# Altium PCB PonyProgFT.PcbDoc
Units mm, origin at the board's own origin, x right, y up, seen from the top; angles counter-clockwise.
Board outline 49.5 x 49.5 mm, 4 copper layers (L1_Top, L2_GND, L3_Power, L4_Bottom), stack 1.543 mm thick; 88 components, 68 nets, 308 pads, 119 vias.
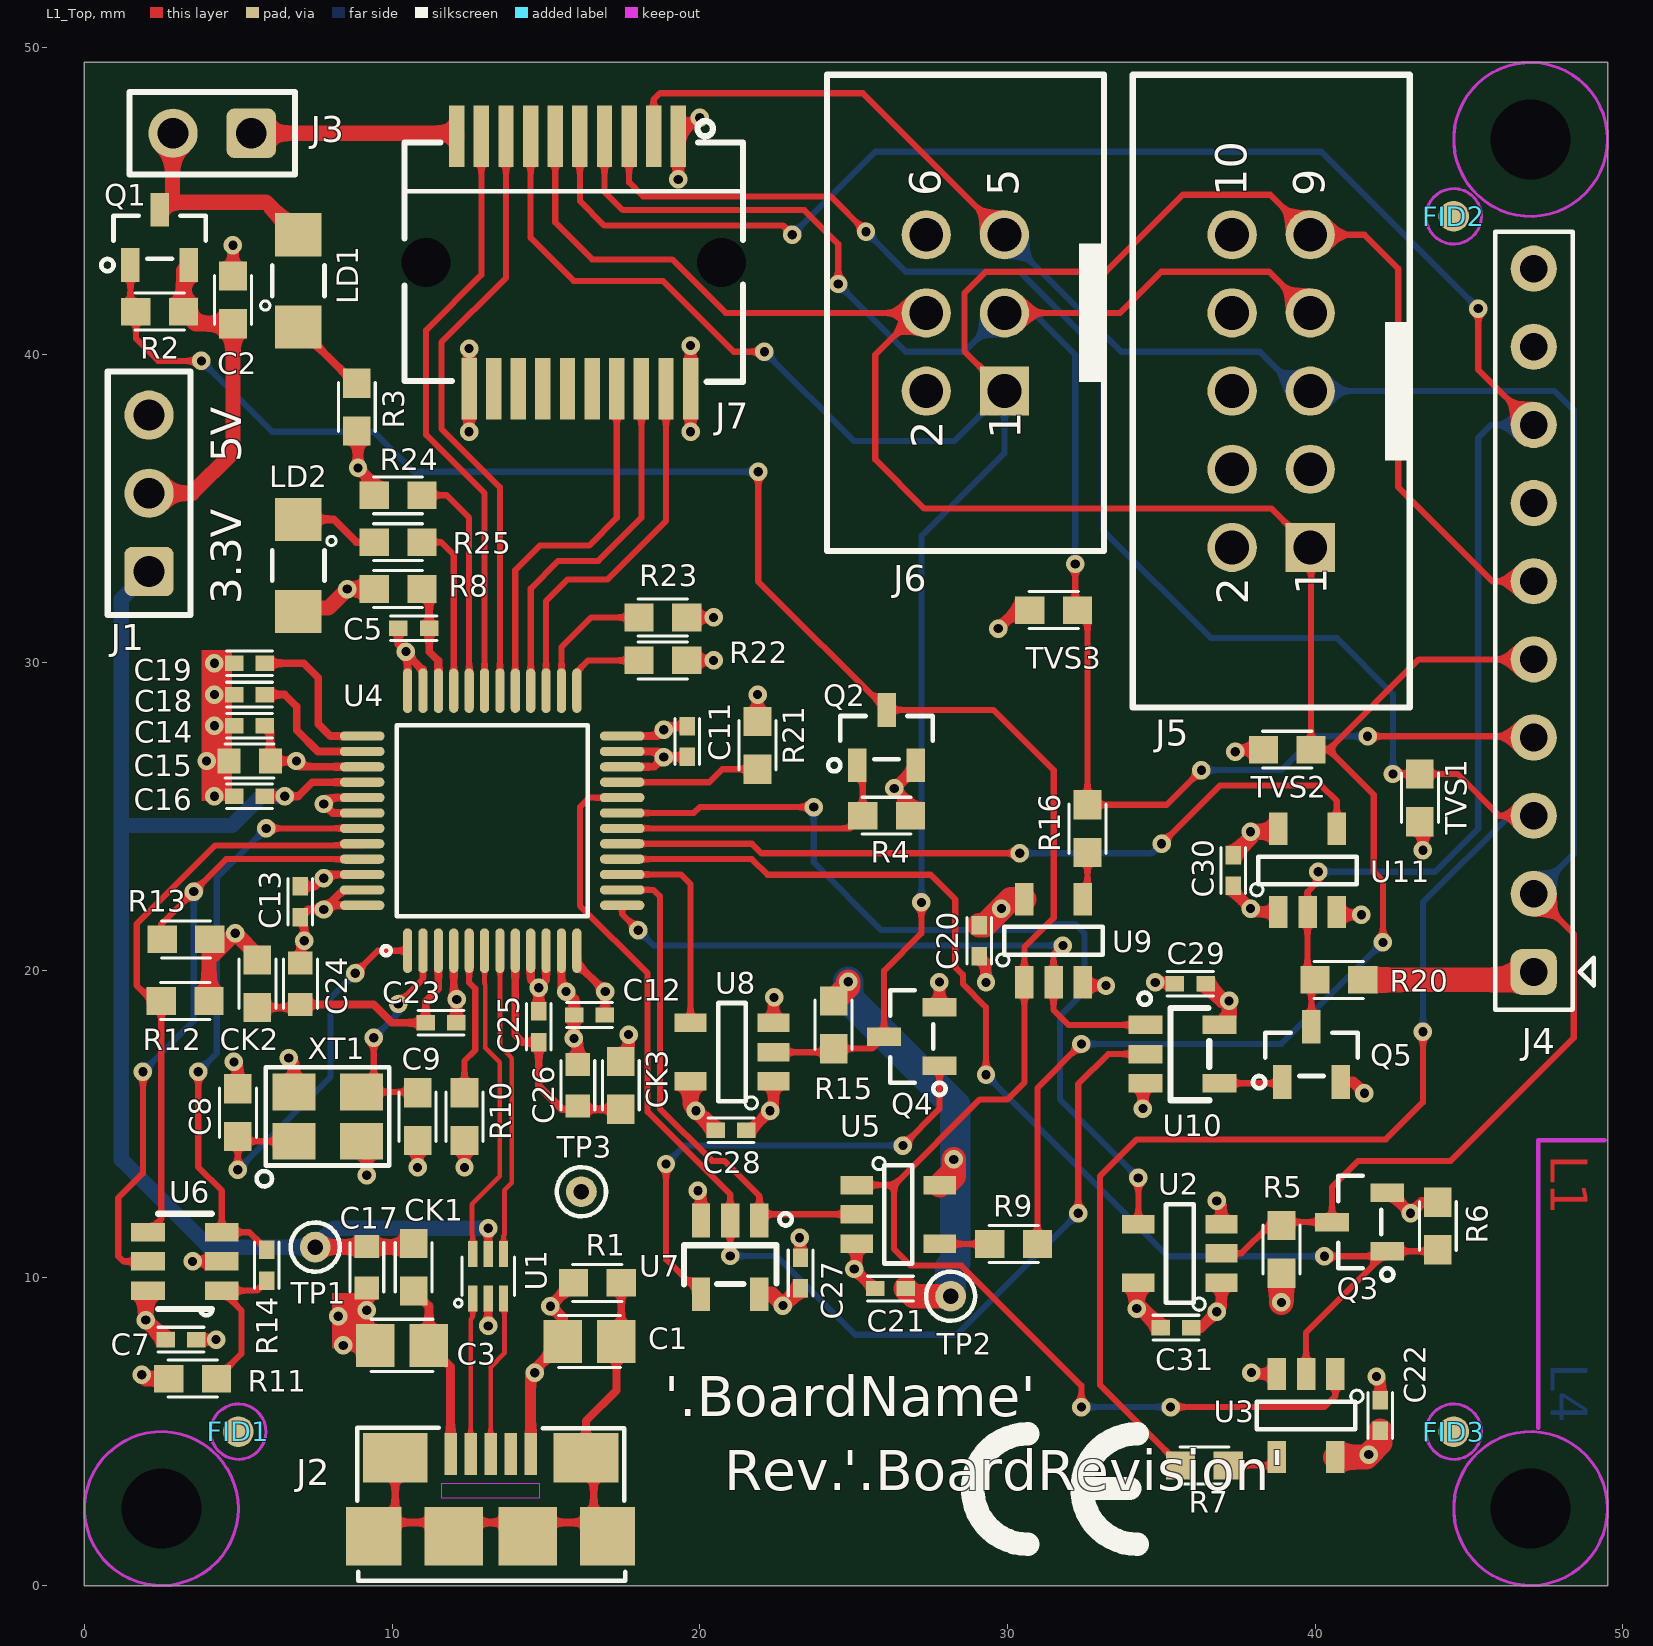
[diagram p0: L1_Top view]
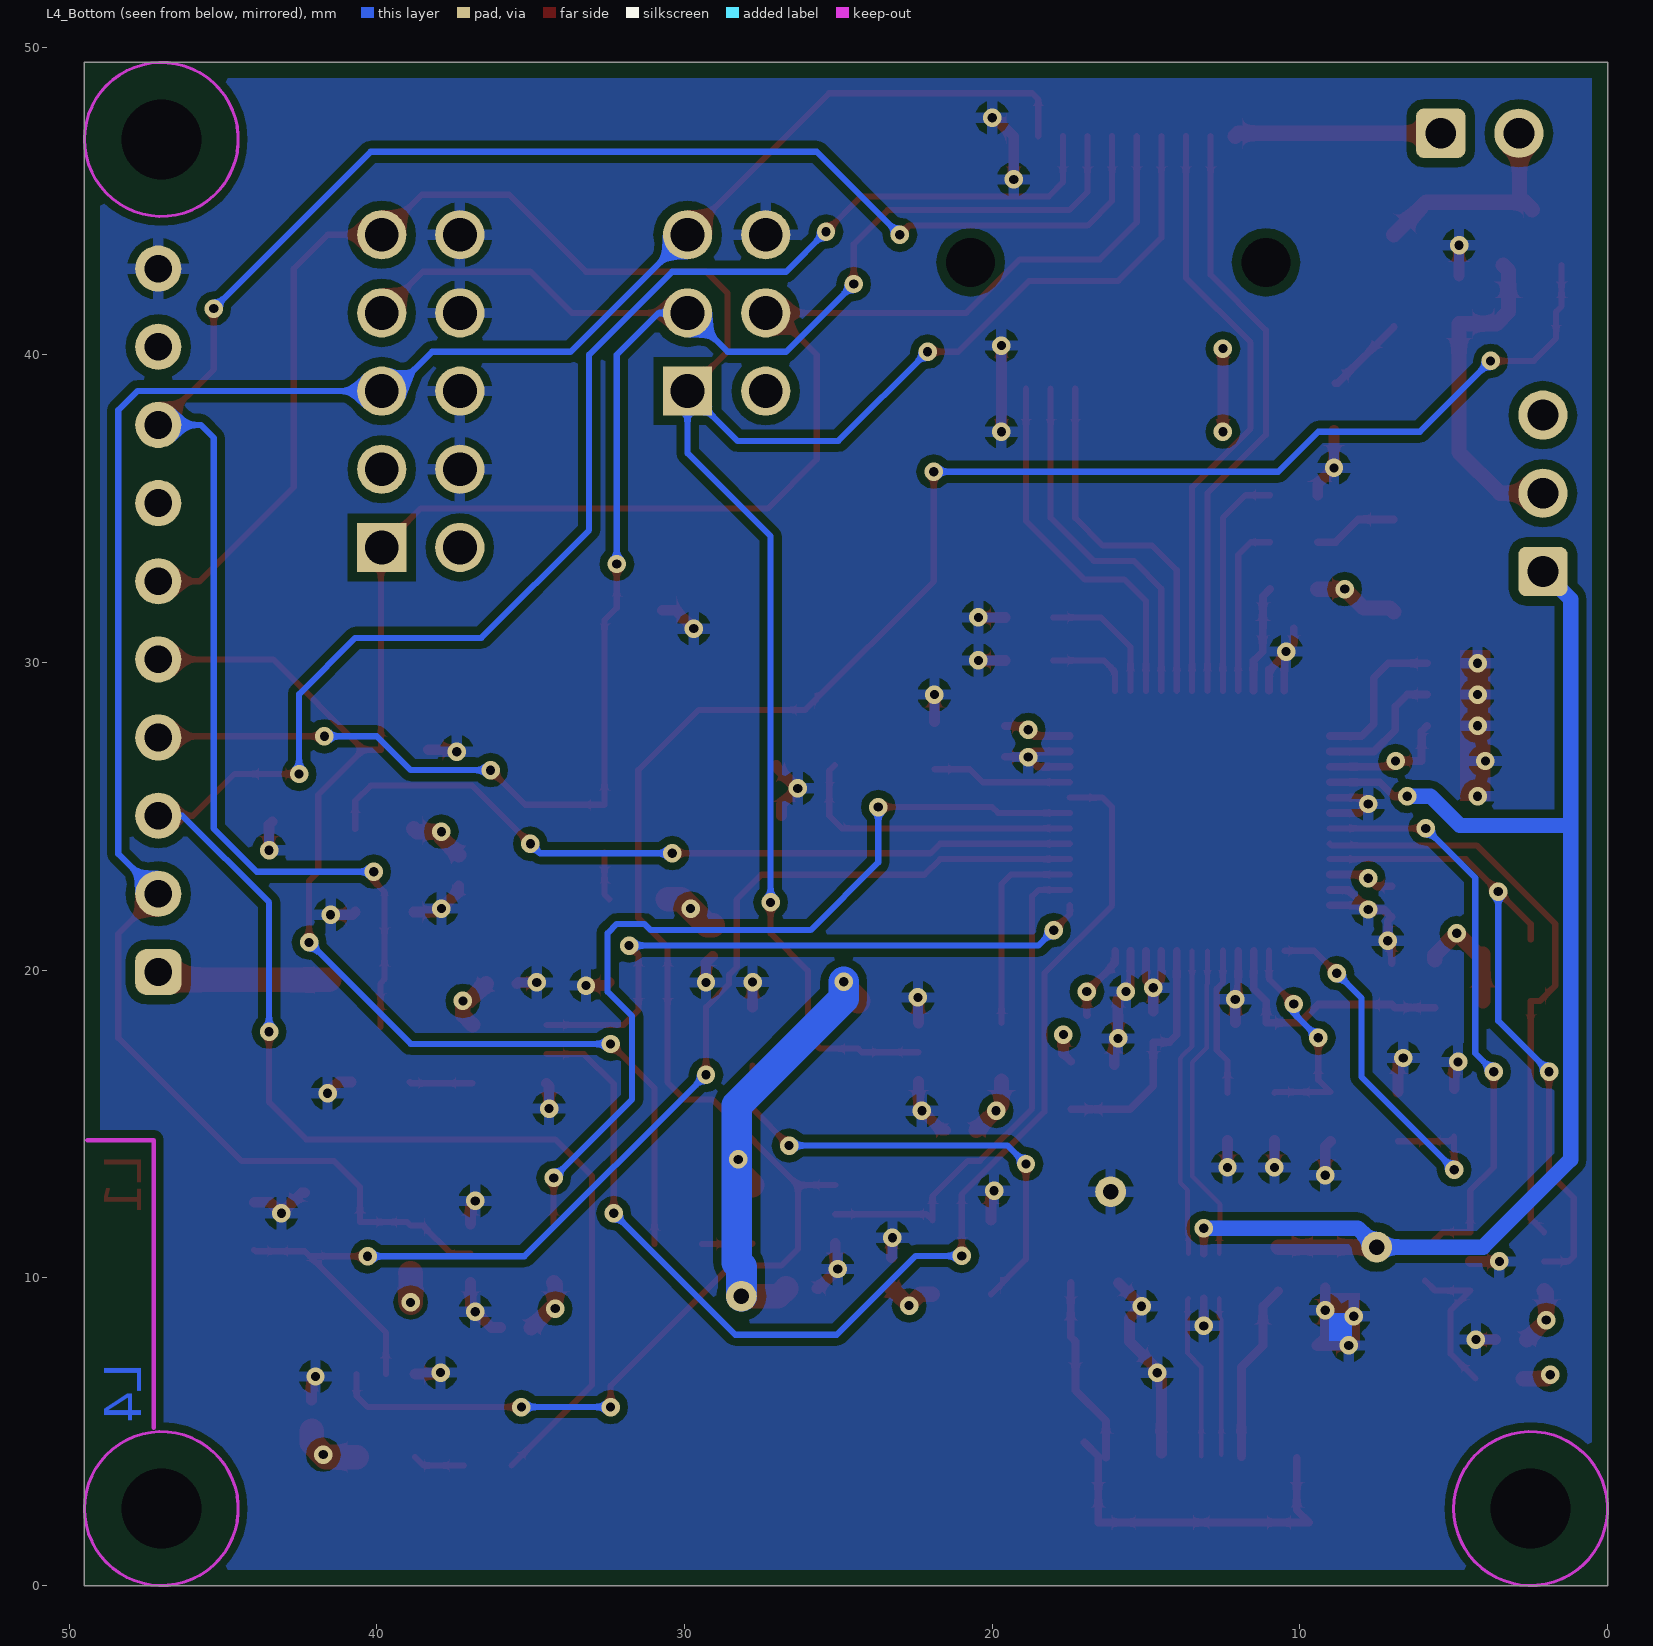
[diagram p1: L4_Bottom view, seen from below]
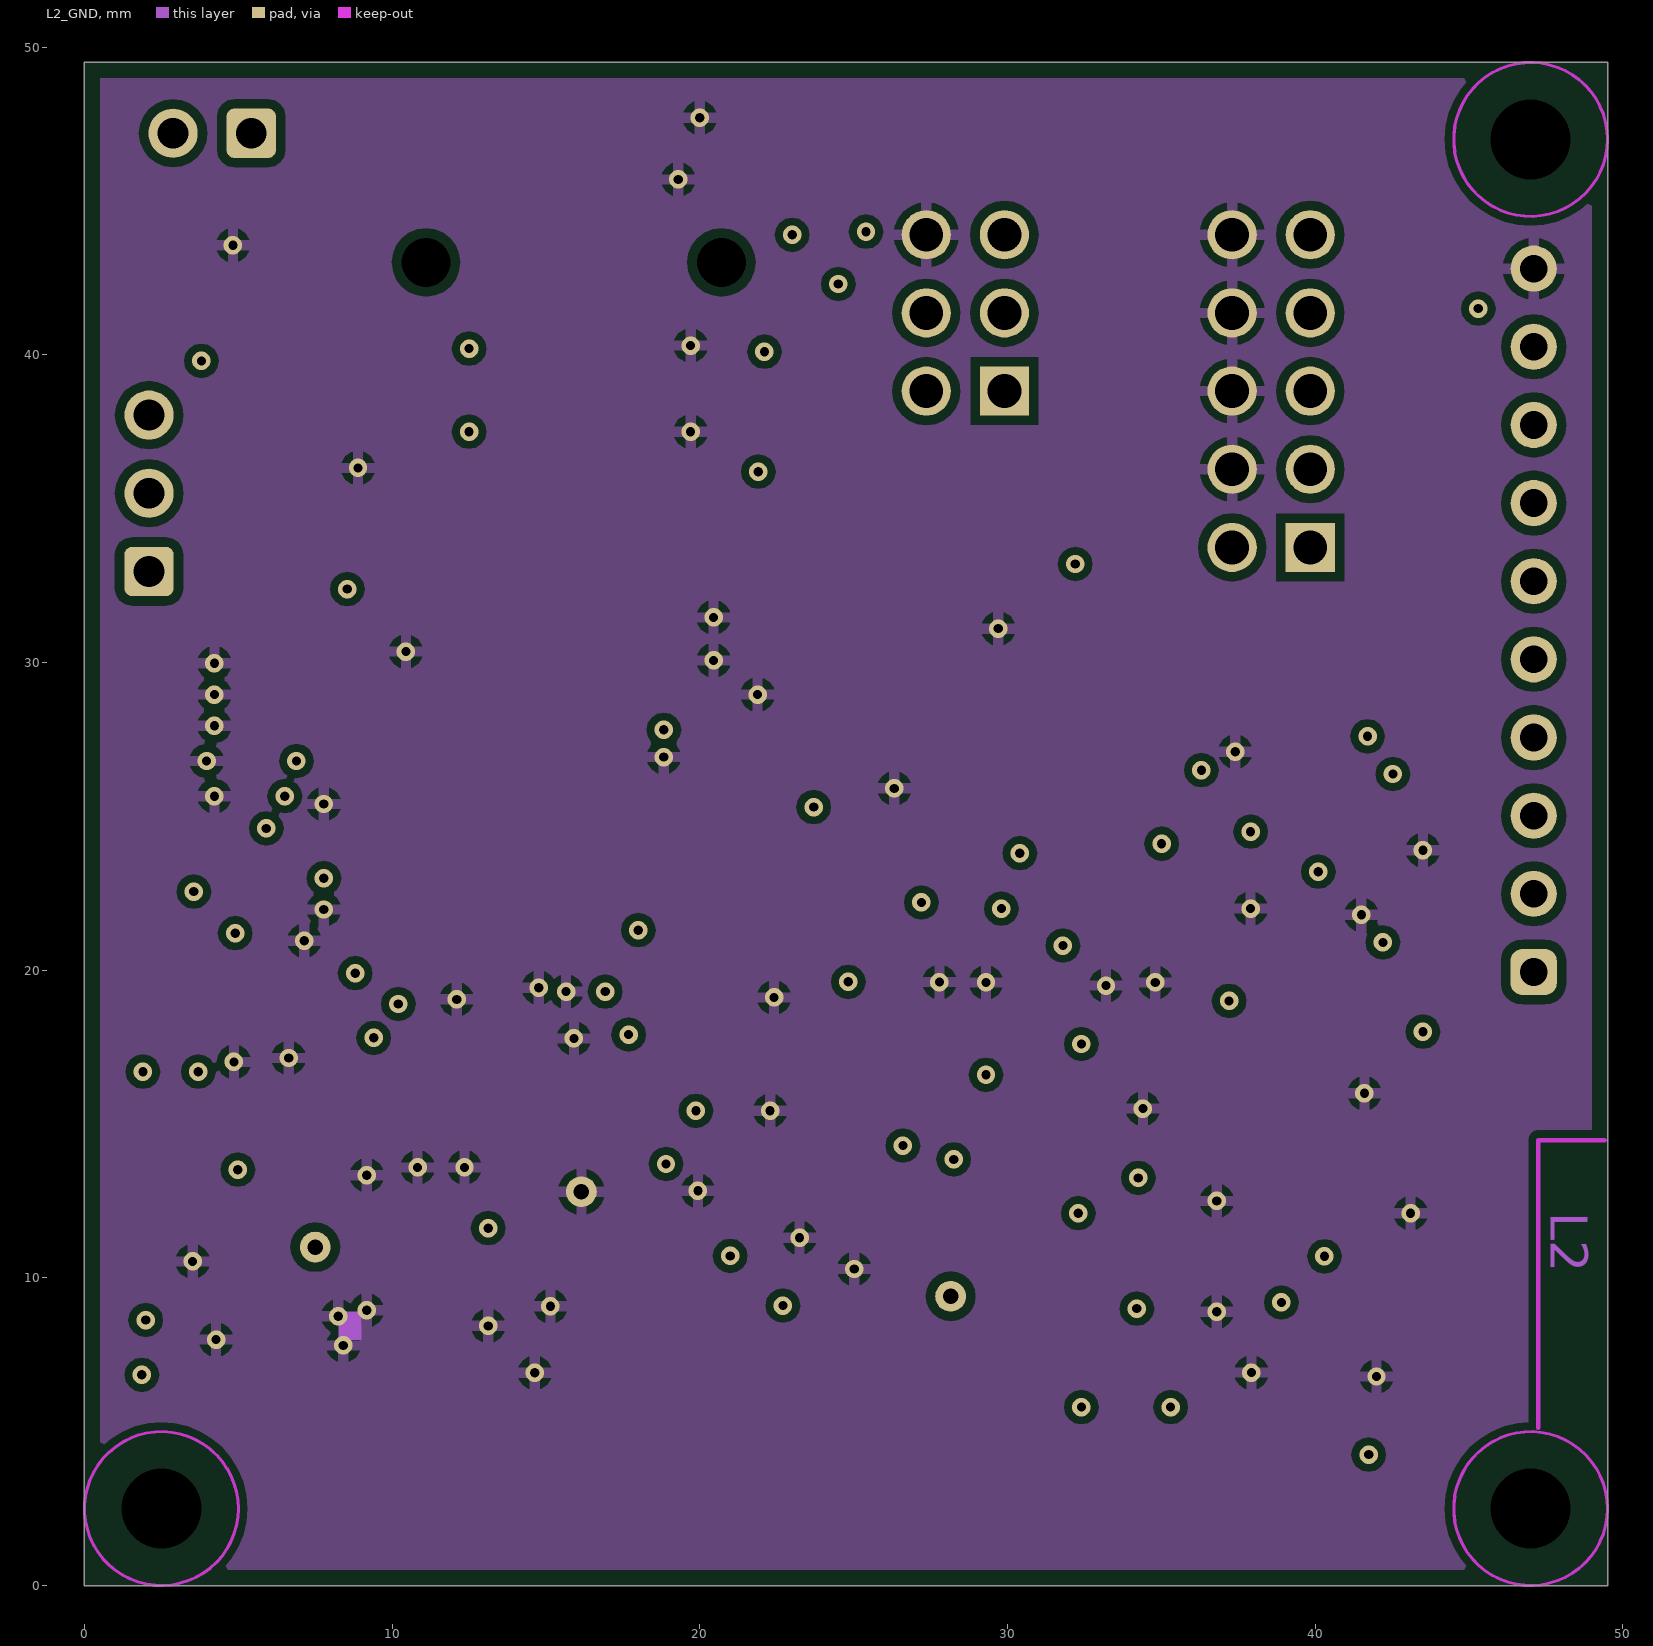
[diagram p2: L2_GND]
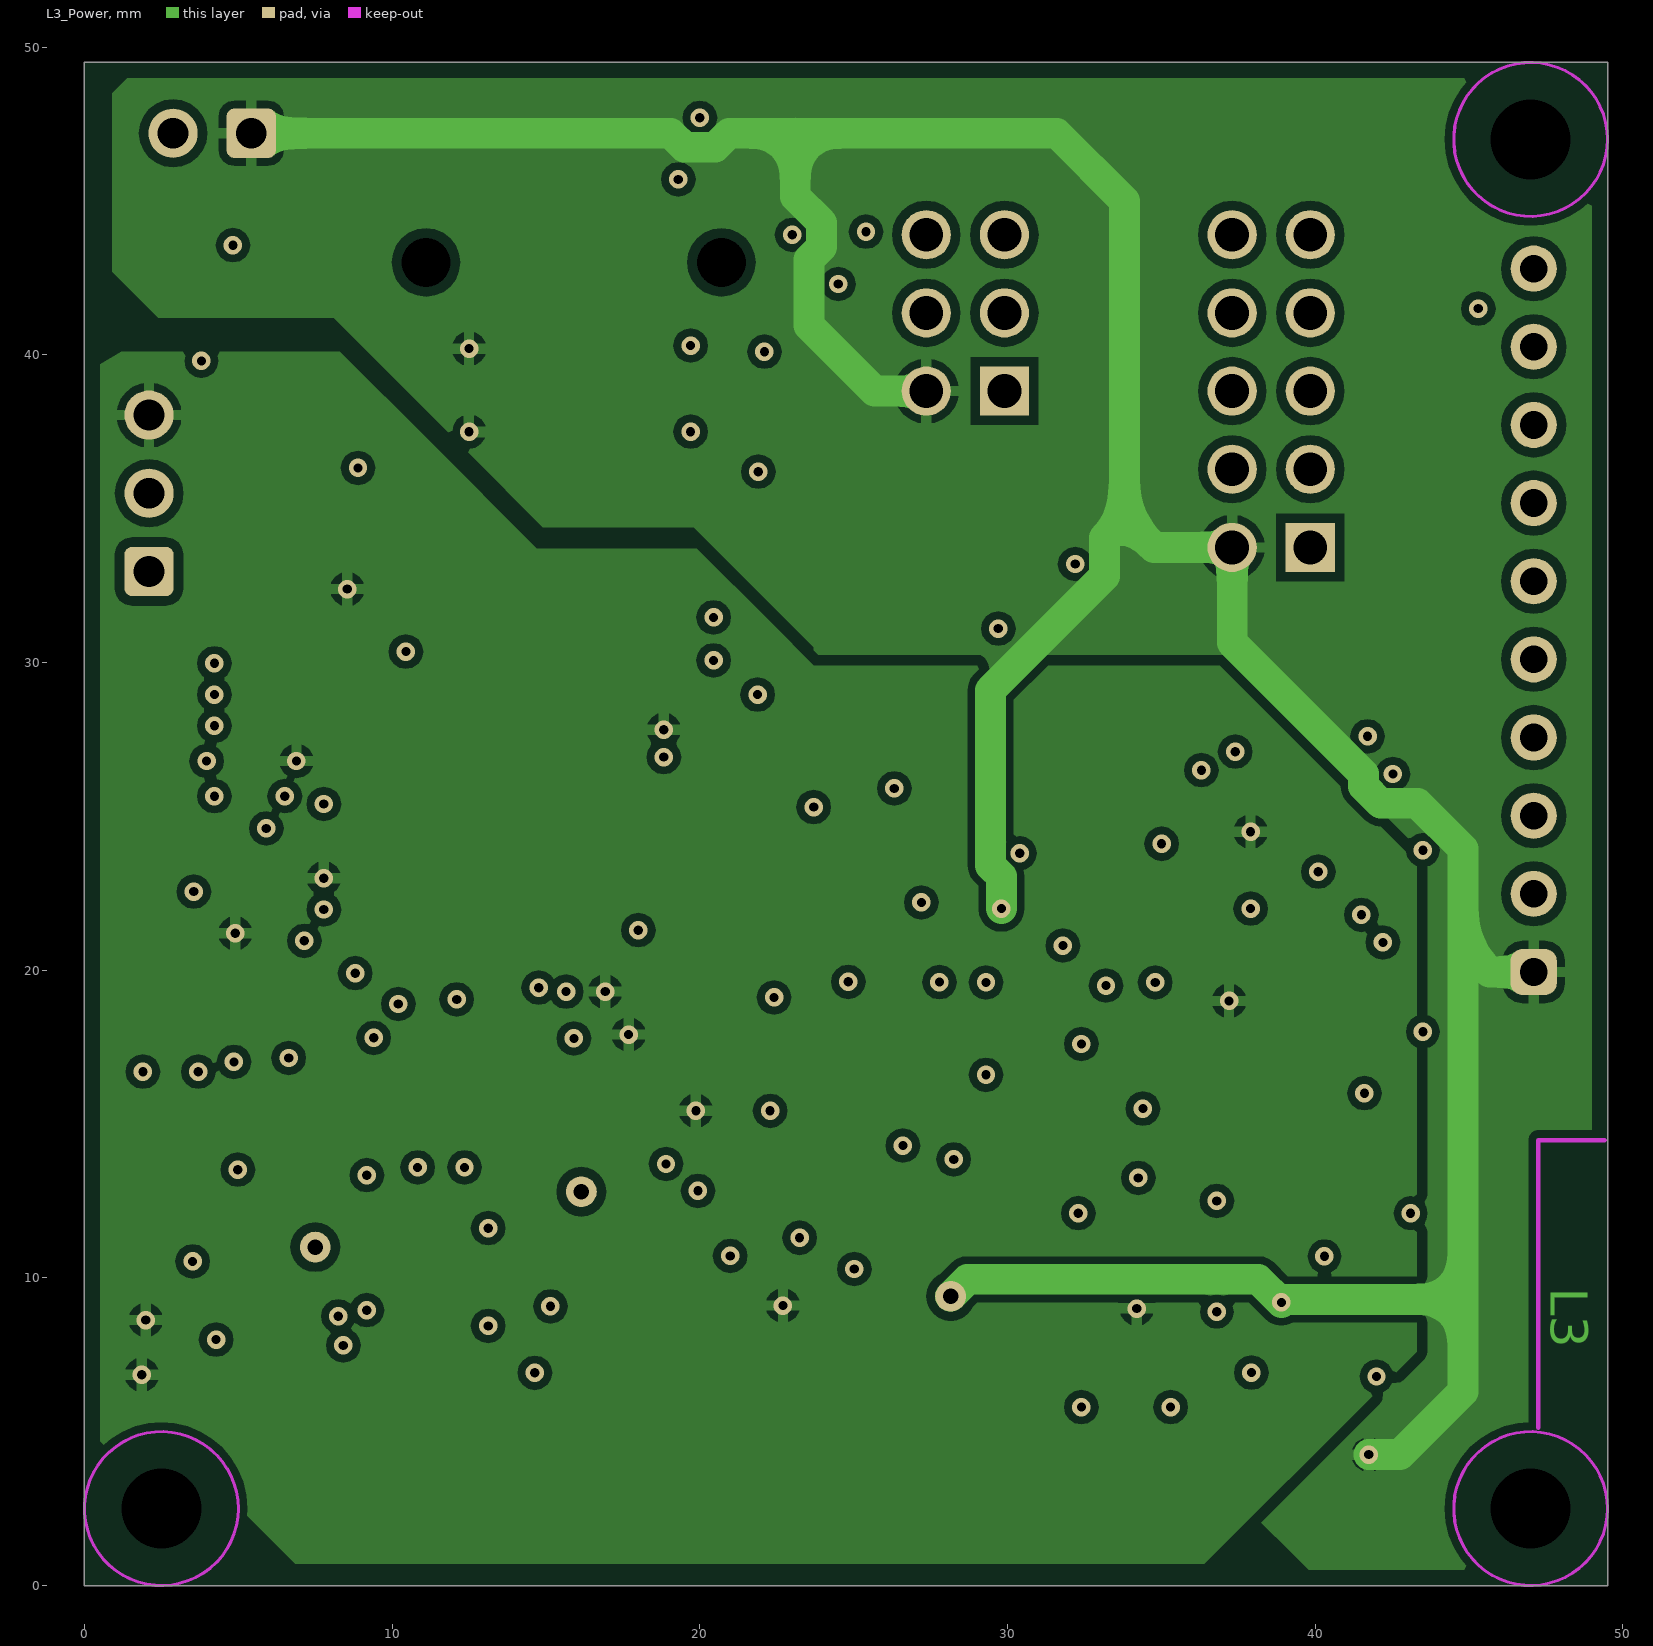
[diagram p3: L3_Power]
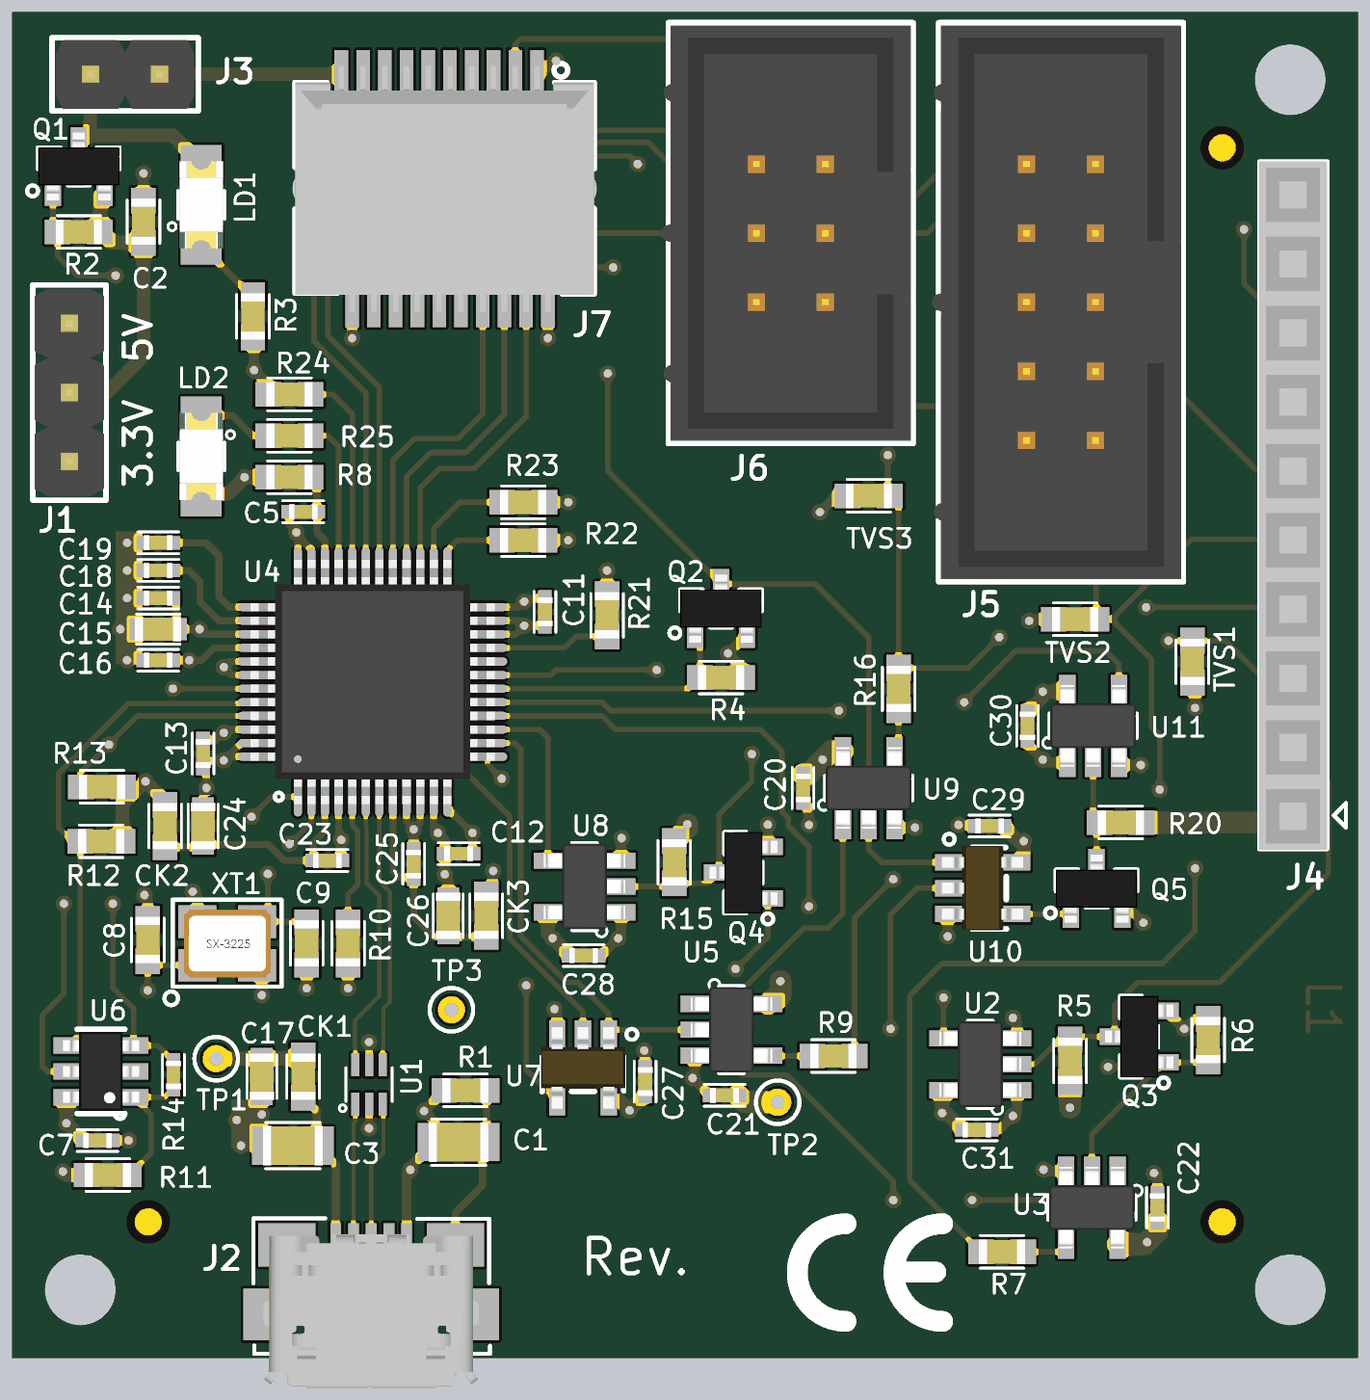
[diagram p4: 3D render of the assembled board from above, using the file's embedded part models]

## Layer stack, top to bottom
Top Solder: solder mask 0.0102, Solder Resist, Dk 3.5
L1_Top: signal copper 0.0356
Dielectric 1: core 0.2, FR-4, Dk 4.2
L2_GND: signal copper 0.036
Dielectric 3: prepreg 1, Dk 4.2
L3_Power: signal copper 0.036
Dielectric 2: core 0.2, Dk 4.2
L4_Bottom: signal copper 0.0356
Bottom Solder: solder mask 0.0102, Solder Resist, Dk 3.5

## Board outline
0,0 0,49.5 49.5,49.5 49.5,0

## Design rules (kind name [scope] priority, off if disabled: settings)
BoardOutlineClearance BoardOutlineClearance_Silk [OnLayer('Top Overlay')] p1: gap=0
BoardOutlineClearance [All] p2: gap=0.5
Clearance Clearance_Poly [All] p1: gap=0.152 except(0.25: Arc-Poly Track-Poly SMDPad-Poly Via-Poly Fill-Poly Poly-Region Poly-Text; 0.3: THPad-Poly; 0.35: Poly-Poly)
Clearance ClearALL [All] p2: gap=0.152
DiffPairsRouting [All] p1: maxlimit=0.152 minlimit=0.152 mostfreqgap=0.152 toplayer_minwidth=0.152 toplayer_maxwidth=0.152 toplayer_prefwidth=0.152 midlayer1_minwidth=0.152 midlayer1_maxwidth=0.152 midlayer1_prefwidth=0.152 midlayer2_minwidth=0.152 midlayer2_maxwidth=0.152 midlayer2_prefwidth=0.152 bottomlayer_minwidth=0.152 bottomlayer_maxwidth=0.152 bottomlayer_prefwidth=0.152 maxuncoupledlength=12.7
HoleSize [All] p1: absolutevalues=TRUE maxlimit=3 minlimit=0.3 maxpercent=80.000 minpercent=20.000
HoleToHoleClearance [All] p1: gap=0.254 allowstackedmicrovias=FALSE
MinimumSolderMaskSliver [All] p1: minsoldermaskwidth=0.04
PolygonConnect [All] p1: connectstyle=Relief reliefconductorwidth=0.35 reliefentries=4 polygonreliefangle="90 Angle" airgapwidth=0.25
RoutingVias [All] p1: holewidth=0.3 width=0.6 viastyle="Through Hole" minholewidth=0.3 minwidth=0.6 maxholewidth=0.5 maxwidth=1
SilkToSilkClearance [All] p1: silktosilkclearance=0.1
SilkToSolderMaskClearance [IsPad] p1: minsilkscreentomaskgap=0.05 clearancetoexposedcopper=TRUE
SolderMaskExpansion [All] p1: expansion=0.102
Width Width_Pwr [InNetClass('NETPWR')] p1: maxlimit=2 minlimit=0.2 preferedwidth=0.254
Width Width_All [All] p2: maxlimit=0.254 minlimit=0.152 preferedwidth=0.152
24 further rules are at their usual default settings.

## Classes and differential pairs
net class USB0: USB0_N USB0_P
net class NETPWR: GND NetC3_1 VCC3V3 VCCIN VCCOUT VCCUSB VPHY VPLL VTG
net class DIFF90: USB0_N USB0_P
differential pair USB0: +USB0_P -USB0_N

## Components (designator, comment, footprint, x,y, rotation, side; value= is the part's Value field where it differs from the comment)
C1 "10nF/50V/0805/10%" C0805_M 16.415,7.931 r180 top
C2 "1uF/10V/0603/10%" C0603_M 4.826,41.783 r90 top
C3 "10nF/50V/0805/10%" C0805_M 10.319,7.804 r180 top
C5 "10nF/25V/0402/10%" C0402_H 10.7,31.115 r180 top
C7 "100nF/16V/0402/10%" C0402_H 3.134,7.993 r0 top
C8 "18pF/50V/0603/5%" C0603_M 4.985,15.367 r270 top
C9 "18pF/50V/0603/5%" C0603_M 10.827,15.24 r90 top
C11 "100nF/16V/0402/10%" C0402_H 19.59,27.432 r270 top
C12 "100nF/16V/0402/10%" C0402_H 16.415,18.542 r180 top
C13 "100nF/16V/0402/10%" C0402_H 7.017,22.225 r270 top
C14 "100nF/16V/0402/10%" C0402_H 5.366,27.94 r180 top
C15 "4.7uF/10V/0603/10%" C0603_H 5.366,26.797 r180 top
C16 "100nF/16V/0402/10%" C0402_H 5.366,25.654 r180 top
C17 "4.7uF/10V/0603/10%" C0603_H 9.176,10.344 r270 top
C18 "100nF/16V/0402/10%" C0402_H 5.366,28.956 r180 top
C19 "100nF/16V/0402/10%" C0402_H 5.366,29.972 r180 top
C20 "100nF/16V/0402/10%" C0402_H 29.083,20.955 r270 top
C21 "100nF/16V/0402/10%" C0402_H 26.194,9.652 r180 top
C22 "100nF/16V/0402/10%" C0402_H 42.118,5.524 r90 top
C23 "100nF/16V/0402/10%" C0402_H 11.589,18.288 r0 top
C24 "4.7uF/10V/0603/10%" C0603_H 7.017,19.558 r90 top
C25 "100nF/16V/0402/10%" C0402_H 14.764,18.161 r90 top
C26 "4.7uF/10V/0603/10%" C0603_H 16.034,16.256 r90 top
C27 "100nF/16V/0402/10%" C0402_H 23.273,10.16 r90 top
C28 "100nF/16V/0402/10%" C0402_H 21.014,14.794 r0 top
C29 "100nF/16V/0402/10%" C0402_H 35.941,19.558 r180 top
C30 "100nF/16V/0402/10%" C0402_H 37.338,23.241 r270 top
C31 "100nF/16V/0402/10%" C0402_H 35.474,8.383 r0 top
CK1 "600@100MHz/1A/0603" C0603_M 10.7,10.344 r270 top
CK2 "600@100MHz/1A/0603" C0603_M 5.62,19.558 r270 top
CK3 "600@100MHz/1A/0603" C0603_M 17.431,16.256 r270 top
FID1 "Fiducial" FID_1MM 5,5 r90 top locked
FID2 "Fiducial" FID_1MM 44.5,44.5 r90 top
FID3 "Fiducial" FID_1MM 44.5,5 r90 top
J1 "61300311121" CON_WE_61300311121 2.1,35.5 r90 top
J2 "10118192-0001LF" CON_FCI_10118192 13.2,1.6 r0 top locked
J3 "61300211121" CON_WE_61300211121 4.15,47.2 r180 top
J4 "75915-310LF" CON_FCI_75915-310LF 47.1,19.94 r90 top locked
J5 "61201021621" CON_WE_61201021621 38.57,38.82 r90 top locked
J6 "61200621621" CON_WE_61200621621 28.63,41.36 r90 top locked
J7 "10056847-101LF" CON_FCI_10056847-101LF 15.9,43 r180 top locked
LD1 "Red" LED_WL-SMCW_1206 6.95,42.4 r90 top
LD2 "Red" LED_WL-SMCW_1206 6.95,33.15 r270 top
Q1 "FDV304P" SOT23-3_H 2.445,43.815 r90 top
Q2 "BSS138" SOT23-3_H 26.067,27.559 r90 top
Q3 "BSS138" SOT23-3_H 41.443,11.812 r180 top
Q4 "BSS138" SOT23-3_H 26.888,17.842 r180 top
Q5 "BSS138" SOT23-3_H 39.878,17.261 r90 top
R1 "100K/1%/0603" C0603_M 16.669,9.836 r180 top
R2 "10K/1%/0603" C0603_M 2.445,41.402 r180 top
R3 "1K/1%/0603" C0603_M 8.85,38.3 r270 top
R4 "10K/1%/0603" C0603_M 26.067,25.019 r0 top
R5 "10K/1%/0603" C0603_M 38.903,10.923 r90 top
R6 "10K/1%/0603" C0603_M 43.983,11.685 r90 top
R7 "100R/1%/0603" C0603_M 36.4,3.9 r180 top
R8 "10K/1%/0603" C0603_M 10.192,32.385 r180 top
R9 "100R/1%/0603" C0603_M 30.2,11.1 r0 top
R10 "12K/1%/0603" C0603_M 12.351,15.24 r90 top
R11 "10K/1%/0603" C0603_M 3.515,6.723 r0 top
R12 "10K/1%/0603" C0603_M 3.272,18.996 r180 top
R13 "10K/1%/0603" C0603_M 3.3,21 r180 top
R14 "2.2K/1%/0402" C0402_H 5.928,10.406 r90 top
R15 "10K/1%/0603" C0603_M 24.348,18.223 r90 top
R16 "100R/1%/0603" C0603_M 32.6,24.6 r90 top
R20 "10K/1%/0603" C0603_M 40.767,19.685 r180 top
R21 "1K/1%/0603" C0603_M 21.876,27.305 r270 top
R22 "1K/1%/0603" C0603_M 18.796,30.067 r180 top
R23 "1K/1%/0603" C0603_M 18.796,31.464 r180 top
R24 "1K/1%/0603" C0603_M 10.192,35.433 r0 top
R25 "1K/1%/0603" C0603_M 10.192,33.909 r180 top
TP1 "non montare" TP-1MM 7.5,11 r90 top
TP2 "non montare" TP-1MM 28.15,9.4 r90 top
TP3 "non montare" TP-1MM 16.15,12.8 r90 top
TVS1 "82356050560" C0603_M 43.4,25.6 r90 top
TVS2 "82356050560" C0603_M 39.092,27.164 r0 top
TVS3 "82356050560" C0603_M 31.5,31.7 r0 top
U1 "USBLC6-2P6" SOT-666_M 13.121,10.053 r90 top
U2 "M74VHC1GT125DT1G" TSOP5-ON 35.601,10.796 r180 top
U3 "M74VHC1GT125DT1G" TSOP5-ON 39.705,5.524 r270 top
U4 "FT232HL" LQFP48_P50_M-STM 13.252,24.858 r90 top
U5 "M74VHC1GT125DT1G" TSOP5-ON 26.448,12.065 r0 top
U6 "93LC56BT-I/OT" SOT23-6_M 3.261,10.533 r180 top
U7 "74LVC1G02GV,125" SOT23-5_M 20.987,10.668 r270 top
U8 "M74VHC1GT125DT1G" TSOP5-ON 21.046,17.334 r180 top
U9 "M74VHC1GT125DT1G" TSOP5-ON 31.496,20.955 r90 top
U10 "74LVC1G02GV,125" SOT23-5_M 35.687,17.272 r0 top
U11 "M74VHC1GT125DT1G" TSOP5-ON 39.751,23.241 r90 top
XT1 "12MHz/Cap/4-SMD, 3.2x2.5mm" XTAL-NX3225SA 7.906,15.24 r0 top

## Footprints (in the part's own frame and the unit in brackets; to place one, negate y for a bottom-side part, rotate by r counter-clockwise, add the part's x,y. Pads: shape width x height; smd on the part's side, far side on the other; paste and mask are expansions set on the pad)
C0402_H [mm] "Chip 2-Leads, Body 1,0x0,5mm, IPC High Density"
  rect 0.6x0.5 smd: 1(-0.5,0) 2(0.5,0)
  silkscreen extent -0.75,-0.4 0.75,0.4, body extent -0.53,-0.28 0.53,0.28, height 0.55
C0603_H [mm] "Chip, 2-Leads, Body 1,6x0,8mm, IPC High Density"
  rect 0.75x0.8 smd: 1(-0.675,0) 2(0.675,0)
  silkscreen extent -0.8,-0.55 0.8,0.55, body extent -0.85,-0.45 0.85,0.45, height 0.9
C0603_M [mm] "Chip 2-Leads, Body 1,6x0,8mm, IPC Medium Density"
  rect 0.95x0.9 smd: 1(-0.775,0) 2(0.775,0)
  silkscreen extent -0.8,-0.6 0.8,0.6, body extent -0.85,-0.45 0.85,0.45, height 0.9
C0805_M [mm] "Chip  2-Leads, Body 2,0x1,3mm, IPC Medium Density"
  rect 1.25x1.4 smd: 1(-0.875,0) 2(0.875,0)
  silkscreen extent -1,-0.85 1,0.85, body extent -1.1,-0.72 1.1,0.73, height 1.35
CON_FCI_75915-310LF [mm]
  rrect50% 1.5x1.5 hole 0.9: 1(0,0)
  round 1.5 hole 0.9: 2(2.54,0) 3(5.08,0) 4(7.62,0) 5(10.16,0) 6(12.7,0) 7(15.24,0) 8(17.78,0) 9(20.32,0) 10(22.86,0)
  silkscreen extent -1.23,-1.95 24.05,1.25, body extent -1.26,-1.25 24.06,1.25, height 8.5
CON_FCI_10056847-101LF [mm]
  round 0.1 hole 1.6 unplated: 0(-4.8,0) 0(4.8,0)
  rect 0.5x2 smd: 1(-3.4,-4.1) 2(-2.6,-4.1) 3(-1.8,-4.1) 4(-1,-4.1) 5(-0.2,-4.1) 6(0.6,-4.1) 7(1.4,-4.1) 8(2.2,-4.1) 9(3,-4.1) 10(3.8,-4.1) 11(3.4,4.1) 12(2.6,4.1) 13(1.8,4.1) 14(1,4.1) 15(0.2,4.1) 16(-0.6,4.1) 17(-1.4,4.1) 18(-2.2,4.1) 19(-3,4.1) 20(-3.8,4.1)
  silkscreen extent -5.5,-4.6 5.5,3.87, body extent -5.5,-4.5 5.5,4.53, height 5.37
CON_FCI_10118192 [mm]
  rect 0.4x1.35 smd: 1(-1.3,2.675) 2(-0.65,2.675) 3(0,2.675) 4(0.65,2.675) 5(1.3,2.675)
  rect 1.8x1.9 smd: S1(-3.8,0) S2(3.8,0)
  rect 2.1x1.6 smd: S1(-3.1,2.55) S2(3.1,2.55)
  rect 1.9x1.9 smd: S1(-1.2,0) S2(1.2,0)
  L1_Top keep-out region: -1.6,1.25 1.6,1.25 1.6,1.7 -1.6,1.7
  silkscreen extent -4.33,-1.45 4.37,3.53, body extent -3.96,-2.72 3.96,2.94, height 2.79
CON_WE_61200621621 [mm] "6 pins, straight, gold plating"
  rect 1.6x1.6 hole 1.1: 1(-2.54,-1.27)
  round 1.6 hole 1.1: 2(-2.54,1.27) 3(0,-1.27) 4(0,1.27) 5(2.54,-1.27) 6(2.54,1.27)
  silkscreen extent -7.74,-4.5 7.74,4.5, body extent -7.64,-4.43 7.64,4.75, height 9.13
CON_WE_61201021621 [mm] "10 pins, straight, gold plating"
  rect 1.6x1.6 hole 1.1: 1(-5.08,-1.27)
  round 1.6 hole 1.1: 2(-5.08,1.27) 3(-2.54,-1.27) 4(-2.54,1.27) 5(0,-1.27) 6(0,1.27) 7(2.54,-1.27) 8(2.54,1.27) 9(5.08,-1.27) 10(5.08,1.27)
  silkscreen extent -10.28,-4.5 10.28,4.5, body extent -10.18,-4.42 10.18,4.75, height 9.13
CON_WE_61300211121 [mm] "Pin Header, pitch 2.54 mm, THT, Vertical, single row, 2p"
  rrect30% 1.6x1.6 hole 1: 1(-1.27,0)
  round 1.6 hole 1: 2(1.27,0)
  silkscreen extent -2.69,-1.35 2.69,1.35, body extent -2.54,-1.27 2.54,1.27, height 8.57
CON_WE_61300311121 [mm] "Pin Header, pitch 2.54 mm, THT, Vertical, single row, 3p"
  rrect30% 1.6x1.6 hole 1: 1(-2.54,0)
  round 1.6 hole 1: 2(0,0) 3(2.54,0)
  silkscreen extent -3.96,-1.35 3.96,1.35, body extent -3.81,-1.27 3.81,1.27, height 8.57
FID_1MM [mm]
  round 1 smd paste-0.5 mask+0.3: 1(0,0)
  L1_Top keep-out circle w0.1: c0,0 r0.9
LED_WL-SMCW_1206 [mm] "SMD Mono-color Chip LED, body 3.2x1.6mm"
  rect 1.4x1.5 smd: A(1.5,0) K(-1.5,0)
  silkscreen extent -0.95,-0.85 0.5,1.22, body extent -1.6,-0.8 1.6,0.8, height 0.7
LQFP48_P50_M-STM [mm] "TSQFP, 48-Leads, Body 7,00x7,00mm, Pitch 0,50mm, IPC Medium Density"
  oval 1.45x0.3 smd: 1(-4.225,2.75) 2(-4.225,2.25) 3(-4.225,1.75) 4(-4.225,1.25) 5(-4.225,0.75) 6(-4.225,0.25) 7(-4.225,-0.25) 8(-4.225,-0.75) 9(-4.225,-1.25) 10(-4.225,-1.75) 11(-4.225,-2.25) 12(-4.225,-2.75) 25(4.225,-2.75) 26(4.225,-2.25) 27(4.225,-1.75) 28(4.225,-1.25) 29(4.225,-0.75) 30(4.225,-0.25) 31(4.225,0.25) 32(4.225,0.75) 33(4.225,1.25) 34(4.225,1.75) 35(4.225,2.25) 36(4.225,2.75)
  oval 0.3x1.45 smd: 13(-2.75,-4.225) 14(-2.25,-4.225) 15(-1.75,-4.225) 16(-1.25,-4.225) 17(-0.75,-4.225) 18(-0.25,-4.225) 19(0.25,-4.225) 20(0.75,-4.225) 21(1.25,-4.225) 22(1.75,-4.225) 23(2.25,-4.225) 24(2.75,-4.225) 37(2.75,4.225) 38(2.25,4.225) 39(1.75,4.225) 40(1.25,4.225) 41(0.75,4.225) 42(0.25,4.225) 43(-0.25,4.225) 44(-0.75,4.225) 45(-1.25,4.225) 46(-1.75,4.225) 47(-2.25,4.225) 48(-2.75,4.225)
  silkscreen extent -4.37,-3.1 3.1,3.6, body extent -4.5,-4.5 4.5,4.5, height 1.6
SOT23-3_H [mm] "SOT23, 3-Leads, Body 3,0x2,5mm (max), Pitch 0,95mm, IPC High Density"
  rect 1.1x0.6 smd: 1(-0.9,0.95) 2(-0.9,-0.95) 3(0.9,0)
  silkscreen extent -1.1,-1.5 0.7,1.9, body extent -1.25,-1.5 1.25,1.5, height 1.13
SOT23-5_M [mm] "SOT23, 5-Leads, Body 3,0x3,0mm (max), Pitch 0,95mm, IPC Medium Density"
  rect 1.1x0.6 smd: 1(-1.2,0.95) 2(-1.2,0) 3(-1.2,-0.95) 4(1.2,-0.95) 5(1.2,0.95)
  silkscreen extent -1.43,-1.5 0.88,2, body extent -1.5,-1.55 1.5,1.55, height 1.1
SOT23-6_M [mm] "SOT23, 6-Leads, Body 3,1x3,0mm (max), Pitch 0,95mm, IPC Medium Density"
  rect 1.1x0.6 smd: 1(-1.2,0.95) 2(-1.2,0) 3(-1.2,-0.95) 4(1.2,-0.95) 5(1.2,0) 6(1.2,0.95)
  silkscreen extent -0.9,-1.55 0.87,1.75, body extent -1.4,-1.45 1.4,1.45, height 1.46
SOT-666_M [mm] "SOT666 (SC-89), 6-Leads, Body 1,7x1,7mm (max), Pitch 0,50mm, IPC Medium Density"
  rect 0.85x0.3 smd: 1(-0.725,0.5) 2(-0.725,0) 3(-0.725,-0.5) 4(0.725,-0.5) 5(0.725,0) 6(0.725,0.5)
  silkscreen extent -1,-0.85 0.62,1.09, body extent -0.63,-0.85 0.63,0.85, height 0.6
TP-1MM [mm] "TP foro=0.5mm pad=1mm"
  round 1 hole 0.5: 1(0,0)
  silkscreen extent -0.8,-0.8 0.8,0.8
TSOP5-ON [mm] "SOT23, 5-Leads, Body 3,00x2,75mm, Pitch 0,95mm, IPC Medium Density"
  rect 1.05x0.6 smd: 1(-1.35,0.95) 2(-1.35,0) 3(-1.35,-0.95) 4(1.35,-0.95) 5(1.35,0.95)
  silkscreen extent -0.82,-1.6 0.45,1.85, body extent -1.5,-1.58 1.5,1.58, height 1.1
XTAL-NX3225SA [mm] "crystal 3.2x2.5mm 4pin"
  rect 1.4x1.2 smd: 1(-1.1,-0.8) 2(1.1,-0.8) 3(1.1,0.8) 4(-1.1,0.8)
  silkscreen extent -2.31,-2.27 2,1.61, body extent -1.68,-1.32 1.69,1.31, height 0.81

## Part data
C1 C3: library part CX7R10N50V10%0805_CL, "Chip Ceramic Capacitor X7R 0805 10nF 50V 10%"
C2: library part CX5R1U10V10%0603_GRM, "Chip Ceramic Capacitor X5R 0603 1uF 10V 10%"
C5: library part CX7R10N25V10%0402_GRM, "Chip Ceramic Capacitor X7R 0402 10nF 25V 10%"
C7 C11 C12 C13 C14 C16 C18 C19 C20 C21 C22 C23 C25 C27 C28 C29 C30 C31: library part CX7R100N16V10%0402_GRM, "Chip Ceramic Capacitor X7R 0402 100nF 16V 10%"
C8 C9: library part CCOG18P50V5%0603_KEMET, "Chip Ceramic Capacitor C0G 0603 18pF 50V 5%"
C15 C17 C24 C26: library part CX5R4.7U10V10%0603_TDK, "Chip Ceramic Capacitor X5R 0603 4.7uF 10V 10%"
CK1 CK2 CK3: library part FCB600Z1A0603MPZ, "Ferrite Chip Beads SMD 0603 600@100MHz 1A"
FID1 FID2 FID3: library part FID, "Fiducial (non montare)"
J1: library part CON_WE_61300311121, "THT Vertical Pin Header Male WR-PHD, Pitch 2.54 mm, Single Row, 3 pins"
J2: library part CON_FCI_10118192-0001LF, "Micro-USB Type-B, right-angle, horizontal receptacle"
J3: library part CON_WE_61300211121, "THT Vertical Pin Header Male WR-PHD, Pitch 2.54 mm, Single Row, 2 pins"
J4: library part CON_FCI_75915-310LF, "CONN RCPT 10POS 0.1 GOLD PCB"
J5: library part CON_WE_61201021621, "Male Box Header WR-BHD, THT, Vertical, pitch 2.54 mm, 10 pins"
J6: library part CON_WE_61200621621, "Male Box Header WR-BHD, THT, Vertical, pitch 2.54 mm, 6 pins"
J7: library part CON_FCI_10056847-101LF, "Connector edge dual female 20 pos, 0.8pitch"
LD1 LD2: library part LED_WE_150120RS75000, "Chip LED SMD WL-SMCW, size 1206, Red, 2V, 140 deg, 150 mcd"
Q1: library part IC_FDV304P, "IC MOSFET P-CH 25V 460mA SOT-23"
Q2 Q3 Q4 Q5: library part IC_BSS138, "MOSFET N-CH 50V 0.22A SOT-23"
R1: library part CRES100K1%100P0603T_CRCW, "Chip Resistor 0603 100K 1% 100ppm"
R2 R4 R5 R6 R8 R11 R12 R13 R15 R20: library part CRES10K1%100P0603T_CRCW, "Chip Resistor 0603 10K 1% 100ppm"
R3 R21 R22 R23 R24 R25: library part CRES1K1%100P0603T_CRCW, "Chip Resistor 0603 1K 1% 100ppm"
R7 R9 R16: library part CRES100R1%100P0603T_CRCW, "Chip Resistor 0603 100R 1% 100ppm"
R10: library part CRES12K1%100P0603T_CRCW, "Chip Resistor 0603 12K 1% 100ppm"
R14: library part CRES2.2K1%100P0402U_CRCW, "Chip Resistor 0402 2.2K 1% 100ppm"
TP1 TP2 TP3: library part TP_TPH-1MM, "Test Point, D=1mm (Foro 0.5mm), non montare"
TVS1 TVS2 TVS3: library part TVSP_WE-82356050560, "Chip ESD suppressor bidirectional 5V 0603"
U1: library part IC_USBLC6-2P6, "TVS 2 line, Low cap, 5V, SOT666"
U2 U3 U5 U8 U9 U11: library part IC_M74VHC1GT125DT, "IC BUFFER NON-INVERT 5.5V 5-TSOP"
U4: library part IC_FT232HL, "IC HS USB TO UART/FIFO 48LQFP"
U6: library part IC_93LC56BT-I/OT, "IC EEPROM 2K SPI 2MHz SOT23-6"
U7 U10: library part IC_74LVC1G02GV, "IC GATE NOR 1CH 2-INP 5-TSOP"
XT1: library part XTAL_NX3225SA-12MHZ-STD-CSR-6, "Xtal SMD 12MHz 8pF 25ppm (-40 to 85)"

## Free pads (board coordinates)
  round 0.1 hole 2.6 unplated: 0(2.5,2.5) 0(47,2.5) 0(47,47)

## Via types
v1: diameter 0.6, hole 0.3, L1_Top to L4_Bottom, tented both sides, 119 vias

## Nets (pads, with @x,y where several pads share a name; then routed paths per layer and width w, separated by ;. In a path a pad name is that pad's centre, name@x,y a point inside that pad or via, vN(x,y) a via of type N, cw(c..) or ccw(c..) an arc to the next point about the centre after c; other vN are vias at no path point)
B_CLK: U4.13 U9.2 U10.1 | length 20.4
  L1_Top w0.2: U4.13 17.477,21.823 v1(18,21.3) ; v1(31.8,20.8) 31.496,20.496 U9.2 31.496,18.704 31.978,18.222 U10.1
  L4_Bottom w0.2: v1(18,21.3) 18.5,20.8 v1(31.8,20.8)
B_CLKIN: U4.17 U11.4 | length 25.4
  L1_Top w0.2: U4.17 21.692,24.108 22,23.8 v1(30.4,23.8) ; v1(35.008,24.108) 36.9,26 40.2,26 40.701,25.499 U11.4
  L4_Bottom w0.2: v1(30.4,23.8) 34.7,23.8 v1(35.008,24.108)
B_CTRL: Q3.1 R6.1 U3.2 U4.16 | length 39.5
  L1_Top w0.2: U4.16 21.692,23.608 22.2,23.1 27.5,23.1 28.3,22.3 28.3,20.1 28.548,19.852 28.548,19.552 29.3,18.8 v1(29.3,16.6) ; U3.2 39.705,8.224 Q3.1@42.181,10.7 ; v1(40.3,10.7) Q3.1@42.181,10.7 ; R6.1 43.935,10.862 Q3.1 Q3.1@42.181,10.7
  L4_Bottom w0.2: v1(29.3,16.6) 35.2,10.7 v1(40.3,10.7)
B_CTRLIN: U2.4 U4.19 | length 28.9
  L1_Top w0.2: U4.19 19.808,25.108 20,25.3 v1(23.7,25.3) ; U2.4 v1(34.251,13.249)
  L4_Bottom w0.2: v1(23.7,25.3) 23.7,23.5 25.9,21.3 31.1,21.3 31.3,21.5 32.2,21.5 32.5,21.2 32.5,19.3 31.7,18.5 31.7,15.8 v1(34.251,13.249)
B_DIN: U4.15 U8.4 | length 6.9
  L1_Top w0.2: U4.15 19.392,23.108 19.696,22.804 U8.4
B_DOUT: U4.14 U5.2 U7.1 | length 16.7
  L1_Top w0.2: U4.14 18.492,22.608 18.7,22.4 18.7,15.5 20.4,13.8 20.8,13.8 21.937,12.663 U7.1 22.134,12.065 U5.2
B_ONOFF: Q2.1 R4.1 U4.18 | length 9.7
  L1_Top w0.2: U4.18 24.881,24.608 R4.1 25.292,26.484 Q2.1
C_CLK: J4.4 J5.7 J6.3 J7.4 R16.2 TVS3.2 | length 62.4
  L1_Top w0.2: J7.4 16.9,45.3 17.5,44.7 23.4,44.7 24.5,43.6 v1(24.5,42.3) ; J6.3 33.66,41.36 35,42.7 38.5,42.7 J5.7 ; v1(32.2,33.2) 32.2,31.775 TVS3.2 32.6,31.375 R16.2 35.175,25.375 v1(36.3,26.5) ; v1(41.7,27.6) 47.06,27.6 J4.4
  L4_Bottom w0.2: v1(24.5,42.3) 26.7,40.1 28.6,40.1 29.86,41.36 J6.3 30.84,41.36 32.2,40 v1(32.2,33.2) ; v1(36.3,26.5) 38.9,26.5 40,27.6 v1(41.7,27.6)
C_CTRL: J4.3 J7.3 R7.2 TVS1.2 | length 77.5
  L1_Top w0.2: J7.3 17.7,45.6 18.152,45.148 24.252,45.148 v1(25.4,44) ; R7.2 33,6.525 33,13.3 34.2,14.5 42.3,14.5 43.5,15.7 v1(43.5,18) ; v1(42.525,26.375) TVS1.2 44.625,26.375 45.98,25.02 J4.3
  L4_Bottom w0.2: v1(25.4,44) 26.7,42.7 30.4,42.7 33.1,40 33.1,34.3 36.6,30.8 40.7,30.8 42.525,28.975 v1(42.525,26.375) ; v1(43.5,18) 43.5,22.2 46.32,25.02 J4.3
C_CTRLOD: J4.2 J5.5 J6.5 J7.2 Q3.3 R5.2 U2.2 | length 71.9
  L1_Top w0.2: J7.2 18.5,48.3 18.7,48.5 25.3,48.5 J6.5 ; U2.2 37.596,10.796 38.498,11.698 R5.2 39.017,11.812 Q3.3 40.543,12.943 41.4,13.8 44.4,13.8 48.4,17.8 48.4,21.18 J4.2
  L4_Bottom w0.2: J6.5 33.7,40.1 38.2,40.1 39.48,38.82 J5.5 47.78,38.82 48.4,38.2 48.4,23.78 J4.2
C_DOUT: J4.5 J5.1 J6.4 J7.6 R9.2 TVS2.2 | length 77
  L1_Top w0.2: J7.6 15.3,44.3 16.5,43.1 19.1,43.1 20.84,41.36 J6.4@27.06,41.36 ; J6.4 J6.4@27.06,41.36 ; R9.2 30.975,16.175 v1(32.4,17.6) ; v1(42.2,20.9) 42.2,22.9 41.9,23.2 41.9,25.7 40.436,27.164 ; J4.5 43.372,30.1 40.436,27.164 ; J6.4@27.06,41.36 25.7,40 25.7,36.6 27.3,35 38.58,35 J5.1 39.867,33.713 TVS2.2 40.436,27.164
  L4_Bottom w0.2: v1(32.4,17.6) 38.9,17.6 v1(42.2,20.9)
C_SCL: J4.8 J7.5 Q5.3 R20.2 U11.2 | length 65.2
  L1_Top w0.2: J7.5 16.1,45 16.9,44.2 22.7,44.2 v1(23,43.9) ; Q5.3 39.878,19.571 39.751,19.698 U11.2 39.751,22.551 40.1,22.9 v1(40.1,23.2) ; v1(45.3,41.5) 45.3,39.52 J4.8
  L4_Bottom w0.2: v1(23,43.9) 25.7,46.6 40.2,46.6 v1(45.3,41.5) ; v1(40.1,23.2) 43.9,23.2 45.3,24.6 45.3,37.3 45.72,37.72 J4.8
C_SDA: J4.6 J5.9 J6.1 J7.7 Q4.3 R15.1 U8.2 | length 81.4
  L1_Top w0.2: J7.7 14.5,43.8 15.9,42.4 18.8,42.4 21.1,40.1 v1(22.1,40.1) ; U8.2 24.234,17.334 R15.1 25.594,17.448 Q4.3 25.988,19.988 27.2,21.2 v1(27.2,22.2) ; J6.1 28.6,40.12 28.6,42 29.3,42.7 33.2,42.7 35.7,45.2 38.54,45.2 J5.9 41.6,43.9 42.7,42.8 42.7,35.7 45.76,32.64 J4.6
  L4_Bottom w0.2: v1(22.1,40.1) 25,37.2 28.28,37.2 J6.1 29.9,36.8 27.2,34.1 v1(27.2,22.2)
EECLK: R12.2 U4.44 U6.4 | length 19.1
  L1_Top w0.2: U6.4 2.497,11.919 R12.2 2.204,18.996 1.7,19.5 1.7,21.5 4.256,24.056 8.975,24.056 U4.44
EECS: R13.2 U4.45 U6.5 | length 21.8
  L1_Top w0.2: v1(1.9,16.7) 1.9,13.4 1.1,12.6 1.1,10.7 1.267,10.533 U6.5 ; R13.2@2.497,21 2.497,21.497 v1(3.552,22.552) 4.608,23.608 U4.45
  L4_Bottom w0.2: v1(1.9,16.7) 3.552,18.353 v1(3.552,22.552)
EEDATA: R14.2 U4.43 U6.3 | length 19.2
  L1_Top w0.2: v1(3.7,16.7) 3.7,13.6 4.461,12.839 U6.3 5.351,11.483 R14.2 ; v1(5.908,24.608) U4.43
  L4_Bottom w0.2: v1(3.7,16.7) 4.3,17.3 4.3,23 v1(5.908,24.608)
EXPID0: J7.19 U4.27 | length 12.2
  L1_Top w0.2: U4.27 15.002,32.002 15.7,32.7 17,32.7 18.9,34.6 J7.19
EXPID1: J7.18 U4.28 | length 12.1
  L1_Top w0.2: U4.28 14.502,32.402 15.4,33.3 16.7,33.3 18.1,34.7 J7.18
EXPID2: J7.17 U4.29 | length 12.1
  L1_Top w0.2: U4.29 14.002,33.002 14.8,33.8 16.4,33.8 17.3,34.7 J7.17
EXPID3: J7.8 U4.30 | length 19.7
  L1_Top w0.2: U4.30 13.502,35.698 11.6,37.6 11.6,40.4 13.7,42.5 J7.8
EXPID4: J7.9 U4.31 | length 19.6
  L1_Top w0.2: J7.9 12.9,42.6 11.1,40.8 11.1,37.4 13.002,35.498 U4.31
GND: C1.2 C2.2 C3.2 C5.2 C7.2 C8.1 C9.1 C11.2 C12.2 C13.2 C14.2 C15.2 C16.2 C17.2 C18.2 C19.2 C20.2 C21.2 C22.2 C23.2 C24.2 C25.2 C26.2 C27.2 C28.2 C29.2 C30.2 C31.2 J2.5 J4.10 J5.4 J5.6 J5.8 J5.10 J6.6 J7.1 J7.20 Q2.2 Q3.2 Q4.2 Q5.2 R1.2 R3.2 R4.2 R6.2 R10.1 R21.1 R22.1 R23.1 R24.1 TP3.1 TVS1.1 TVS2.1 TVS3.1 U1.2 U2.1 U2.3 U3.3 U4.4 U4.9 U4.10 U4.11 U4.22 U4.23 U4.35 U4.36 U4.41 U4.42 U4.47 U4.48 U5.3 U6.2 U7.3 U8.1 U8.3 U9.3 U10.3 U11.1 U11.3 XT1.2 XT1.4 | length 78.8
  L1_Top w0.25: C24.2 7.017,20.828 v1(7.144,20.955) 7.144,21.598 C13.2 7.263,21.971 v1(7.779,21.971) v1@7.916,22.108 ; U4.48 v1@7.916,22.108 ; U4.47 8.416,22.608 v1@7.916,22.108 ; U4.42 8.071,25.108 v1(7.779,25.4) 7.987,25.608 U4.41 ; C5.2 10.2,30.599 v1(10.446,30.353) 10.446,30.298 v1@10.502,30.242 ; U4.36 v1@10.502,30.242 ; U4.35 11.002,29.776 10.969,29.776 v1@10.502,30.242 ; U4.4 12.002,19.129 v1@12.089,19.042 ; v1(13.121,8.439) U1.2 ; U4.9 14.502,19.693 v1(14.764,19.431) 15.002,19.669 U4.10 ; U4.11 15.502,19.455 v1(15.653,19.304) ; U4.22 18.512,26.608 v1(18.828,26.924) ; U4.23 18.644,27.108 v1(18.828,26.924) ; C11.2 18.836,26.932 v1(18.828,26.924)
  L1_Top w0.35: v1(3.515,10.533) U6.2 ; C7.2 v1(4.277,7.993) ; C2.2 v1(4.826,43.561) ; v1(4.858,17.018) 4.985,16.891 C8.1 ; v1(6.636,17.145) 6.806,16.975 XT1.4 ; v1(8.414,7.804) C3.2 9.176,8.072 v1(9.176,8.947) C17.2 ; R3.2@8.89,37.543 v1(8.89,36.322) 9.417,35.795 R24.1 ; XT1.2 9.176,14.27 v1(9.176,13.335) ; v1(10.827,13.589) C9.1 ; C23.2 v1@12.089,19.042 ; v1(12.351,13.589) R10.1 ; J2.5@14.5,4.3 14.5,6.778 v1(14.637,6.915) 14.637,7.028 C1.2 15.54,8.692 15.145,9.087 R1.2 ; C25.2 v1(14.764,19.431) ; v1(15.653,19.304) 15.915,19.042 C12.2 15.907,18.534 v1(15.907,17.78) 16.034,17.653 C26.2 ; v1(19.3,45.7) J7.1 19.9,47.7 v1(20,47.7) ; R22.1 v1(20.447,30.067) ; R23.1 v1(20.447,31.464) ; v1(19.7,37.5) v1(19.7,40.3) ; v1(19.939,12.827) 20.037,12.729 U7.3 ; C28.2 21.649,14.794 v1(22.284,15.429) 22.396,15.541 U8.1 ; R21.1 v1(21.876,28.956) ; U8.3 22.396,19.097 v1(22.411,19.112) ; v1(23.241,11.303) 23.273,11.271 C27.2 ; U5.3 25.098,10.366 v1(25.019,10.287) 25.654,9.652 C21.2 ; R4.2 26.842,25.387 v1(26.321,25.908) 27.017,26.604 Q2.2 ; Q4.2 v1(27.788,19.612) ; C20.2 29.3,20.238 v1(29.3,19.6) ; v1(29.7,31.1) 30.3,31.7 TVS3.1 ; U9.3 32.551,19.5 v1(33.2,19.5) ; v1(34.4,15.5) 34.4,16.235 U10.3 ; v1(34.8,19.6) 35.399,19.6 C29.2 ; C31.2 36.283,8.383 v1(36.8,8.9) 36.951,9.051 U2.1 ; v1(36.8,12.5) 36.951,12.349 U2.3 ; C30.2 37.338,22.562 v1(37.9,22) 38.009,21.891 U11.1 ; v1(37.4,27.1) 37.464,27.164 TVS2.1 ; v1(37.927,6.921) 37.974,6.874 U3.3 ; U11.3 40.792,21.8 v1(41.5,21.8) ; Q5.2 41.239,16.361 v1(41.6,16) ; v1(41.991,6.794) 42.118,6.667 C22.2 ; Q3.2 42.438,12.762 v1(43.1,12.1) 43.46,12.46 R6.2 ; TVS1.1 43.5,24.725 v1(43.5,23.9)
  other v1: 8.25,8.75 15.145,9.074 12.097,19.05 4.223,25.654 3.969,26.797 4.223,27.94 4.223,28.956 4.223,29.972
NEN_BUS: U4.20 U7.2 U10.2 | length 38.9
  L1_Top w0.2: U4.20 16.408,25.608 16.1,25.3 16.1,22.1 18.3,19.9 18.3,15.4 20.987,12.713 U7.2 v1(20.987,10.713) ; v1(32.3,12.1) 32.3,16.3 33.272,17.272 U10.2
  L4_Bottom w0.2: v1(20.987,10.713) 22.487,10.713 25.05,8.15 28.35,8.15 v1(32.3,12.1)
NetC1_1: C1.1 J2.S1 J2.S2 R1.1 | length 18.1
  L1_Top w0.25: C1.1@17.444,8.085 R1.1
  L1_Top w0.254: J2.S1@10.1,4.15 10.1,2.45 9.7,2.05 16.55,2.05 16.55,4.2 J2.S2@17,4.65 ; J2.S2@16.3,4.15 16.3,5.35 17.29,6.34 C1.1 C1.1@17.444,8.085
NetC3_1: C3.1 CK1.2 J2.1 | length 5.9
  L1_Top w0.3: CK1.2 11.194,9.075 C3.1 11.9,7.098 J2.1 J2.1@11.9,4.2
NetC5_1: C5.1 R8.1 U4.34 | length 3.5
  L1_Top w0.254: R8.1 11.2,32.152 C5.1 11.208,31.107 11.208,30.353 11.502,30.059 U4.34
NetC8_2: C8.2 U4.1 XT1.1 | length 12.9
  L1_Top w0.2: v1(4.985,13.515) C8.2 5.137,14.44 XT1.1 ; v1(8.8,19.9) 9.533,20.633 U4.1
  L4_Bottom w0.2: v1(4.985,13.515) 8,16.53 8,19.1 v1(8.8,19.9)
NetC9_2: C9.2 U4.2 XT1.3 | length 7.3
  L1_Top w0.2: v1(9.4,17.8) 9.4,16.434 XT1.3 10.802,16.04 C9.2 ; v1(10.2,18.9) 11.002,19.702 U4.2
  L4_Bottom w0.2: v1(9.4,17.8) 10.2,18.6 v1(10.2,18.9)
NetFID1_1: FID1.1
NetFID2_1: FID2.1
NetFID3_1: FID3.1
NetJ2_4: J2.4
NetJ4_7: J4.7
NetJ4_9: J4.9
NetJ5_3: J5.3
NetJ7_12: J7.12
NetJ7_13: J7.13
NetJ7_14: J7.14
NetJ7_15: J7.15
NetJ7_16: J7.16
NetLD1_K: LD1.K R3.1 | length 2.7
  L1_Top w0.254: LD1.K 8.775,39.075 R3.1
NetLD2_K: LD2.K R25.2 | length 2.8
  L1_Top w0.254: LD2.K 8.103,34.65 8.844,33.909 R25.2
NetQ4_1: Q4.1 U7.4 | length 15.7
  L1_Top w0.2: v1(18.9,13.7) 18.9,10.605 U7.4 ; v1(26.6,14.3) 27.788,15.488 Q4.1
  L4_Bottom w0.2: v1(18.9,13.7) 19.5,14.3 v1(26.6,14.3)
NetQ5_1: Q5.1 U10.4 | length 2.1
  L1_Top w0.2: U10.4 38.889,16.322 Q5.1
NetR7_1: R7.1 U3.4 | length 1.7
  L1_Top w0.2: R7.1 38.481,3.9 U3.4
NetR9_1: R9.1 U5.4 | length 1.6
  L1_Top w0.2: U5.4 27.813,11.1 R9.1
NetR10_2: R10.2 U4.5 | length 4.8
  L1_Top w0.2: R10.2 12.351,17.051 12.7,17.4 12.7,19.4 12.502,19.598 U4.5
NetR11_2: R11.2 R14.1 U6.1 | length 5.1
  L1_Top w0.2: R11.2 5.1,7.533 5.1,8.944 U6.1 5.605,9.583 R14.1
NetR16_1: R16.1 U9.4 | length 1.6
  L1_Top w0.2: U9.4 32.6,22.459 R16.1
NetR21_2: R21.2 U4.21 | length 4.6
  L1_Top w0.2: U4.21 20.308,26.108 20.73,26.53 R21.2
NetR22_2: R22.2 U4.25 | length 2.8
  L1_Top w0.2: U4.25 16.002,29.702 16.367,30.067 R22.2
NetR23_2: R23.2 U4.26 | length 4.3
  L1_Top w0.2: U4.26 15.502,30.502 16.464,31.464 R23.2
NetR24_2: R24.2 U4.32 | length 7.5
  L1_Top w0.2: R24.2 11.767,35.433 12.502,34.698 U4.32
NetR25_1: R25.1 U4.33 | length 5.6
  L1_Top w0.2: R25.1 11.591,33.909 12.002,33.498 U4.33
NOE: Q1.1 Q2.3 R2.2 U3.1 U5.1 U9.1 | length 77.4
  L1_Top w0.2: Q1.1 1.495,41.577 R2.2 1.67,40.53 2.4,39.8 v1(3.8,39.8) ; v1(21.9,36.2) 21.9,32.626 Q2.3 29.541,28.459 31.5,26.5 31.5,21.7 30.546,20.746 U9.1 30.546,16.346 30,15.8 29.1,15.8 26.315,13.015 ; U5.1 26.315,13.015 ; v1(32.4,5.8) 32.4,6.5 28.502,10.398 26.852,10.398 26.315,10.935 26.315,13.015 ; v1(35.3,5.8) 40.3,5.8 40.655,6.155 U3.1
  L4_Bottom w0.2: v1(3.8,39.8) 6.1,37.5 9.4,37.5 10.7,36.2 v1(21.9,36.2) ; v1(32.4,5.8) v1(35.3,5.8)
USB0_N: U1.6 U4.6 | length 10.4
  L1_Top w0.152: U1.6 12.621,11.367 12.593,11.395 12.593,12.393 13.5,13.3 13.5,17 13.028,17.472 13.028,19.536 13.002,19.562 U4.6
USB0_P: U1.4 U4.7 | length 10.1
  L1_Top w0.152: U4.7 13.502,17.528 13.8,17.23 13.889,17.141 13.889,13.089 13.649,12.849 13.649,11.395 13.621,11.367 U1.4
USB_A_N: J2.2 U1.1 | length 5.1
  L1_Top w0.152: J2.2@12.55,4.25 J2.2 12.55,8.65 12.621,8.721 U1.1
USB_A_P: J2.3 U1.3 | length 5.3
  L1_Top w0.152: J2.3@13.2,4.2 J2.3 13.2,7.1 13.65,7.55 13.65,9.299 U1.3
VCC3V3: C7.1 C11.1 C12.1 C13.1 C14.1 C15.1 C27.1 C28.1 C29.1 C30.1 C31.1 CK2.1 CK3.1 J1.3 LD2.A R8.2 R11.1 R12.1 R13.1 U2.5 U4.12 U4.24 U4.39 U4.46 U6.6 U7.5 U8.5 U10.5 U11.5 | length 30.9
  L1_Top w0.254: C14.1 6.041,27.765 C15.1 v1(6.89,26.797) 7.079,26.608 U4.39 ; C13.1 7.517,22.725 v1(7.779,22.987) 7.9,23.108 U4.46 ; U4.12 16.002,20.225 v1(16.923,19.304) 16.923,18.55 C12.1 ; CK3.1 CK3.1@17.685,17.285 ; U4.24 18.623,27.608 v1(18.828,27.813) 18.947,27.932 C11.1
  L1_Top w0.35: CK3.1@17.685,17.285 v1(17.685,17.907)
  L1_Top w0.5: v1(1.864,6.85) 1.991,6.723 R11.1 ; U6.6 1.991,9.513 v1(1.991,8.628) 2.626,7.993 C7.1 ; R12.1 4.047,20.52 4.22,20.52 v1(4.9,21.2) 5.62,20.48 CK2.1 ; LD2.A 7.072,31.772 7.928,31.772 v1(8.541,32.385) R8.2 ; U8.5 19.696,15.604 v1(19.871,15.429) 19.879,15.429 C28.1 ; U7.5 22.332,9.468 v1(22.7,9.1) 23.26,9.66 C27.1 ; U2.5 34.2,9.795 v1(34.2,9) 34.357,9 C31.1 ; C29.1 36.999,19 v1(37.2,19) 37.2,18.535 U10.5 ; C30.1 37.9,24.303 v1(37.9,24.5) 38.71,24.5 U11.5
VCCA: C19.1 U4.37 | length 5
  L1_Top w0.254: C19.1 7.128,29.972 7.6,29.5 7.6,28 7.992,27.608 U4.37
VCCIN: C2.1 J1.2 Q1.2 R2.1 | length 10.8
  L1_Top w0.5: J1.2 3.5,35.5 4.826,36.826 C2.1 3.614,41.008 R2.1 3.22,42.74 Q1.2
VCCOUT: J3.2 LD1.A Q1.3 | length 7.4
  L1_Top w0.5: Q1.3 Q1.3@2.688,44.958 ; J3.2@2.86,47.2 2.86,45.13 Q1.3@2.688,44.958 ; LD1.A 5.892,44.958 Q1.3@2.688,44.958
VCCUSB: C16.1 C17.1 CK1.1 J1.1 TP1.1 U1.5 U4.40 | length 45.9
  L1_Top w0.25: C16.1 v1(6.509,25.654) 6.954,25.654 7.408,26.108 U4.40 ; U1.5 v1(13.121,11.614)
  L1_Top w0.5: TP1.1 CK1.1@10.7,11
  L4_Bottom w0.5: J1.1 1.2,32.06 1.2,24.7 ; v1(6.509,25.654) 5.754,25.654 4.8,24.7 1.2,24.7 ; v1(13.121,11.614) 8.114,11.614 TP1.1 4.041,11 1.198,13.844 1.198,24.698 1.2,24.7
VCORE: C18.1 U4.38 | length 4.4
  L1_Top w0.254: C18.1 6.509,28.956 6.9,28.565 6.9,27.8 7.592,27.108 U4.38
VPHY: C23.1 C24.1 CK2.2 U4.3 | length 8.3
  L1_Top w0.25: CK2.2 6.917,18.783 C24.1 9.4,18.883 9.995,18.288 C23.1 11.089,18.989 11.502,19.402 U4.3
VPLL: C25.1 C26.1 CK3.2 U4.8 | length 8
  L1_Top w0.25: U4.8 14.002,17.898 14.239,17.661 C25.1 14.764,16.236 15.519,15.481 CK3.2
VTG: C20.1 C21.1 C22.1 J3.1 J4.1 J5.2 J6.2 J7.10 J7.11 R5.1 R15.2 R20.1 TP2.1 U3.5 U5.5 U9.5 | length 160.4
  L1_Top w0.35: v1(12.5,37.5) J7.11 v1(12.5,40.2)
  L1_Top w0.5: J3.1@5.4,47.2 J3.1 12,47.2 J7.10
  L1_Top w0.8: R15.2 24.824,19.474 v1(24.824,19.62) ; C21.1 26.946,9.4 TP2.1 ; U5.5 28.067,13.284 28.067,13.117 28.25,13.3 v1(28.25,13.85) ; C20.1 29.255,21.455 v1(29.8,22) 30.105,22.305 U9.5 ; v1(38.9,9.2) 38.9,10.145 R5.1 ; U3.5 41.657,4.174 v1(41.737,4.254) 42.118,4.635 C22.1 ; R20.1 46.845,19.685 J4.1
  L3_Power w1: J3.1@5.4,47.2 J3.1 19.048,47.2 19.5,46.748 20.5,46.748 20.952,47.2 23.1,47.2 ; J6.2 25.68,38.82 23.548,40.952 23.548,43.101 23.952,43.506 23.952,44.294 23.1,45.147 23.1,47.2 ; TP2.1 28.702,9.952 38.148,9.952 v1(38.9,9.2) 39,9.3 44.8,9.3 ; v1(29.8,22) 29.8,23.053 29.448,23.406 29.448,29.101 33.152,32.806 33.152,34.052 33.8,34.7 ; v1(41.737,4.254) 42.754,4.254 44.8,6.3 44.8,9.3 ; J4.1 45.66,19.94 44.8,20.8 ; 23.1,47.2 31.6,47.2 33.8,45 33.8,34.7 ; 33.8,34.7 34.76,33.74 J5.2 37.3,30.653 41.573,26.381 41.573,25.981 42.131,25.423 43.324,25.423 44.8,23.947 44.8,20.8 ; 44.8,9.3 44.8,20.8
  L4_Bottom w1: v1(24.824,19.62) 24.824,19.076 28.3,15.6 28.3,10.5 28.15,10.35 TP2.1
pads on no net: J7.0

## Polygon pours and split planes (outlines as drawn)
GND on L2_GND "L2_GNDPoly" (solid, remove dead copper, pour order 0): -0.6,50.3 -0.3,50 50.3,50 50.3,-1.2 50.4,-1.3 49.9,-0.8 -0.5,-0.8
VTG on L3_Power "L3_VtgPoly" (solid, remove dead copper, pour order 4): 4.3,49.3 46.1,49.3 47.2,48.2 49.1,46.3 49.1,43.3 49.1,2.6 48.2,1.7 46.7,0.2 44.1,0.2 40.1,0.2 39.2,1.1 37.5,2.8 28.6,2.8 27.7,2.8 24.4,6.1 23.7,6.8 23.7,12.2 23.7,30.5 23.3,30.9 19.8,34.4 14.9,34.4 8.6,40.7 8.1,41.2 3.5,41.2 2.4,41.2 1.1,42.5 0.9,42.7 0.9,48.3 0.9,48.5 1.7,49.3
VCC3V3 on L3_Power "L3_VCC3Poly" (solid, remove dead copper, pour order 2): 1.2,40.1 8.3,40.1 11.2,37.2 14.7,33.7 18.4,33.7 19.9,33.7 22.3,31.3 23.7,29.9 35.7,29.9 36.9,29.9 43.3,23.5 43.3,17.6 43.3,7.6 36.4,0.7 21.8,0.7 6.85,0.7 5.35,2.2 3,2.2 0.3,4.9 0.2,5 0.2,39.5
GND on L4_Bottom "L4_GNDPoly" (solid, remove dead copper, pour order 6): -0.3,50 -0.25,50.05 50,50.05 50,-0.2 49.8,-0.4 49.6,-0.2 -0.6,-0.2

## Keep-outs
Keep-Out Layer:
  circle w0.1: c47,47 r2.5
  circle w0.1: c47,2.5 r2.5
  circle w0.1: c2.5,2.5 r2.5
  lines w0.15: 47.25,5.125 47.25,14.45 ; 47.25,14.475 49.4,14.475

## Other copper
L1_Top:
  rectangle net GND: 8.05,7.7 9.15,9.5
  rectangle net GND: 3.8,25.5 4.8,30.4
  text "L1" at 47.65,14 h1.2 r270
L2_GND:
  rectangle net GND: 8.25,7.979 9.001,8.9
  text "L2" at 47.65,12.138 h1.2 r270
L3_Power:
  text "L3" at 47.65,9.675 h1.2 r270
L4_Bottom:
  rectangle net GND: 8.3,7.95 9.05,8.85
  text "L4" at 47.65,7.225 h1.2 r270

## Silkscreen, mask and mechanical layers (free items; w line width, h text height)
Top Overlay:
  lines w0.762: 30.663,1.34 cw(c30.663,3.136) 30.663,4.932 ; 32.441,3.154 33.965,3.154 ; 34.219,1.34 cw(c34.219,3.136) 34.219,4.932
  text "5V" at 5.1,36.5 h1 r90
  text "3.3V" at 5.1,31.9 h1 r90
  text "'.BoardName'" at 18.85,5.5 h1.3
  text "Rev." at 20.8,3.1 h1.3
  text "'.BoardRevision'" at 24.65,3.1 h1.3
Mechanical 1:
  the board outline again, w0.1
AssemblyTOP:
  text "'.Layer_Name'" at 23.15,50.15 h0.85
  text "'.BoardRevision'" at 14.5,50.1 h0.85
  text "Rev." at 11.8,50.067 h0.85
  text "'.BoardName'" at 3.1,50.05 h0.85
